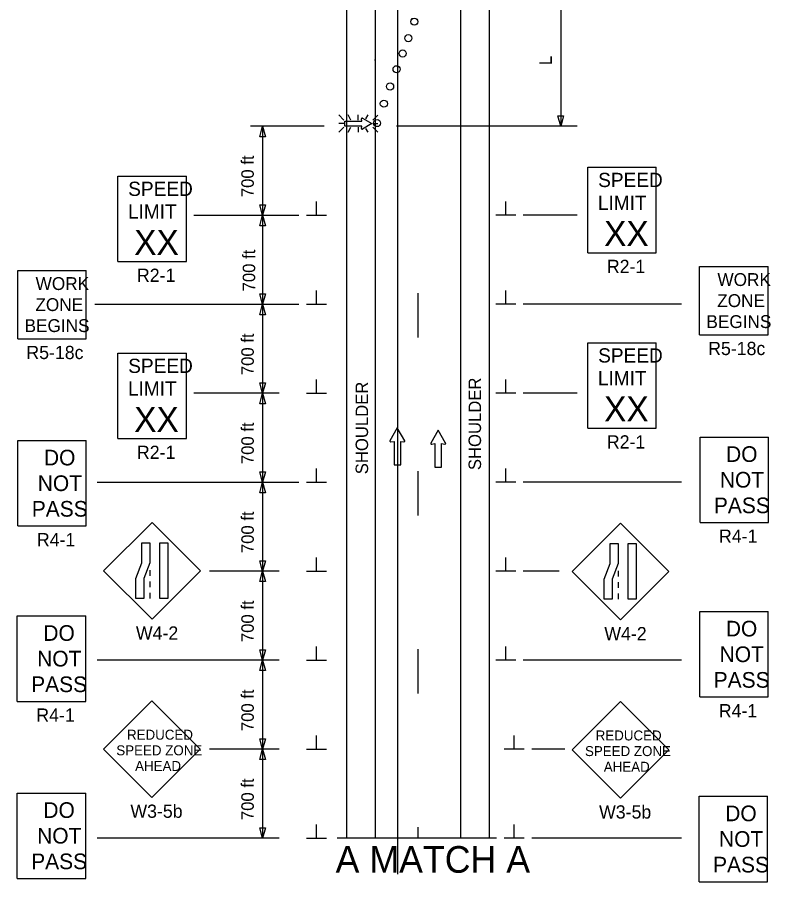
# Model space of a CAD drawing. Extents: x 15262 to 18126, y 1908 to 6555.
# Drawn here: x 15368.1 to 15791.2, y 2404.3 to 2890 of the extents above; entities that cross this region are included whole.
import ezdxf

# ---------------------------------------------------------------- set-up
doc = ezdxf.new("R2010")
doc.units = 0
for name, color, linetype in [('ALI_LEGAL_EX', 7, 'Continuous'), ('MT_SCRATCH_LEVEL_E', 7, 'Continuous'), ('PAVT_EDGE_EX', 7, 'Continuous'), ('TRAFFIC_SIGNS_PR', 7, 'Continuous'), ('TYPICAL_TEXT_DIMEN_PR', 7, 'Continuous')]:
    doc.layers.add(name, color=color, linetype=linetype)

msp = doc.modelspace()

# ---------------------------------------------------------------- linework, layer by layer
at = {"layer": 'ALI_LEGAL_EX'}
msp.add_line((15581.68, 3237.79), (15581.68, 2408.6), dxfattribs=at)
for points in [[(15593, 2735), (15593, 2710)], [(15593, 2635), (15593, 2610)], [(15593, 2535), (15593, 2510)], [(15593, 2435), (15593, 2428.74)]]:
    msp.add_lwpolyline(points, dxfattribs=at)
at = {"layer": 'MT_SCRATCH_LEVEL_E'}
for p, q in [((15581.51, 2659.29), (15577.39, 2652.05)), ((15585.65, 2652.05), (15581.51, 2659.29)), ((15604.48, 2658.02), (15600.37, 2650.78)), ((15608.63, 2650.78), (15604.48, 2658.02)), ((15577.88, 2651.37), (15579.65, 2651.68)), ((15579.65, 2651.68), (15579.65, 2638.43)), ((15583.4, 2638.43), (15583.4, 2651.68)), ((15583.4, 2651.68), (15585.17, 2651.37)), ((15600.85, 2650.1), (15602.63, 2650.41)), ((15602.63, 2650.41), (15602.63, 2637.16)), ((15606.37, 2637.16), (15606.37, 2650.41)), ((15606.37, 2650.41), (15608.15, 2650.1)), ((15579.65, 2638.43), (15583.4, 2638.43)), ((15602.63, 2637.16), (15606.37, 2637.16))]:
    msp.add_line(p, q, dxfattribs=at)
for centre, start, end in [((15577.8, 2651.83), 150.4248, 279.9638), ((15585.24, 2651.83), 260.0362, 29.7731), ((15600.78, 2650.56), 150.4248, 279.9638), ((15608.22, 2650.56), 260.0362, 29.7731)]:
    msp.add_arc(centre, 0.463, start, end, dxfattribs=at)
at = {"layer": 'PAVT_EDGE_EX'}
for p, q in [((15553, 3162.29), (15553, 2428.74)), ((15569, 3162.29), (15569, 2428.74)), ((15617, 3162.29), (15617, 2428.74)), ((15633, 3163.21), (15633, 2428.74)), ((15589.94, 2889.37), (15589.89, 2889.49)), ((15568.93, 2865.92), (15568.88, 2866.04))]:
    msp.add_line(p, q, dxfattribs=at)
at = {"layer": 'TRAFFIC_SIGNS_PR'}
for p, q in [((15551.53, 2832.24), (15548.71, 2835.07)), ((15555.48, 2832.24), (15553.85, 2835.07)), ((15559.62, 2832.24), (15559.62, 2835.07)), ((15563.8, 2832.88), (15565.06, 2835.07)), ((15570.52, 2835.06), (15567.7, 2832.24)), ((15551.53, 2830.21), (15548.71, 2830.21)), ((15551.53, 2828.18), (15548.71, 2825.36)), ((15553.83, 2825.36), (15555.46, 2828.18)), ((15559.62, 2828.18), (15559.62, 2825.36)), ((15565.09, 2825.36), (15563.88, 2827.45)), ((15567.7, 2830.21), (15570.52, 2830.21)), ((15570.52, 2825.36), (15567.7, 2828.18)), ((15688.51, 2805.71), (15726.91, 2805.71)), ((15688.51, 2757.71), (15688.51, 2805.71)), ((15726.91, 2757.71), (15726.91, 2805.71)), ((15424.65, 2800.74), (15463.05, 2800.74)), ((15424.65, 2752.74), (15424.65, 2800.74)), ((15463.05, 2752.74), (15463.05, 2800.74)), ((15688.51, 2757.71), (15726.91, 2757.71)), ((15424.65, 2752.74), (15463.05, 2752.74)), ((15751.25, 2711.62), (15751.25, 2750.02)), ((15751.25, 2750.02), (15789.65, 2750.02)), ((15789.65, 2711.62), (15789.65, 2750.02)), ((15368.42, 2709.37), (15368.42, 2747.77)), ((15368.42, 2747.77), (15406.82, 2747.77)), ((15406.82, 2709.37), (15406.82, 2747.77)), ((15751.25, 2711.62), (15789.65, 2711.62)), ((15368.42, 2709.37), (15406.82, 2709.37)), ((15688.51, 2707.12), (15726.91, 2707.12)), ((15688.51, 2659.12), (15688.51, 2707.12)), ((15726.91, 2659.12), (15726.91, 2707.12)), ((15424.65, 2701.27), (15463.05, 2701.27)), ((15424.65, 2653.27), (15424.65, 2701.27)), ((15463.05, 2653.27), (15463.05, 2701.27)), ((15688.51, 2659.12), (15726.91, 2659.12)), ((15368.48, 2604.2), (15368.48, 2652.2)), ((15368.48, 2652.2), (15406.88, 2652.2)), ((15406.88, 2604.2), (15406.88, 2652.2)), ((15424.65, 2653.27), (15463.05, 2653.27)), ((15751.47, 2606.14), (15751.47, 2654.14)), ((15751.47, 2654.14), (15789.87, 2654.14)), ((15789.87, 2606.14), (15789.87, 2654.14)), ((15368.48, 2604.2), (15406.88, 2604.2)), ((15443.79, 2606.06), (15416.63, 2578.91)), ((15470.94, 2578.91), (15443.79, 2606.06)), ((15706.79, 2605.7), (15679.64, 2578.54)), ((15733.95, 2578.54), (15706.79, 2605.7)), ((15751.47, 2606.14), (15789.87, 2606.14)), ((15416.63, 2578.91), (15443.79, 2551.75)), ((15442.54, 2579.4), (15442.54, 2576.2)), ((15443.79, 2551.75), (15470.94, 2578.91)), ((15705.55, 2579.03), (15705.55, 2575.83)), ((15679.64, 2578.54), (15706.79, 2551.39)), ((15706.79, 2551.39), (15733.95, 2578.54)), ((15442.54, 2573), (15442.54, 2569.8)), ((15705.55, 2572.63), (15705.55, 2569.43)), ((15442.54, 2566.6), (15442.54, 2563.4)), ((15705.55, 2566.23), (15705.55, 2563.03)), ((15751.34, 2508.09), (15751.34, 2556.09)), ((15751.34, 2556.09), (15789.74, 2556.09)), ((15789.74, 2508.09), (15789.74, 2556.09)), ((15368.14, 2505.63), (15368.14, 2553.63)), ((15368.14, 2553.63), (15406.54, 2553.63)), ((15406.54, 2505.63), (15406.54, 2553.63)), ((15751.34, 2508.09), (15789.74, 2508.09)), ((15368.14, 2505.63), (15406.54, 2505.63)), ((15443.68, 2505.95), (15416.53, 2478.8)), ((15470.84, 2478.8), (15443.68, 2505.95)), ((15706.83, 2505.53), (15679.68, 2478.37)), ((15733.99, 2478.37), (15706.83, 2505.53)), ((15416.53, 2478.8), (15443.68, 2451.64)), ((15443.68, 2451.64), (15470.84, 2478.8)), ((15679.68, 2478.37), (15706.83, 2451.22)), ((15706.83, 2451.22), (15733.99, 2478.37)), ((15368.14, 2406.14), (15368.14, 2454.14)), ((15368.14, 2454.14), (15406.54, 2454.14)), ((15406.54, 2406.14), (15406.54, 2454.14)), ((15751, 2404.3), (15751, 2452.3)), ((15751, 2452.3), (15789.4, 2452.3)), ((15789.4, 2404.3), (15789.4, 2452.3)), ((15368.14, 2406.14), (15406.54, 2406.14)), ((15751, 2404.3), (15789.4, 2404.3))]:
    msp.add_line(p, q, dxfattribs=at)
for points in [[(15561.44, 2827.53), (15561.67, 2828.83), (15551.95, 2828.83), (15551.95, 2831.57), (15561.67, 2831.57), (15561.44, 2832.87)], [(15561.94, 2833.23), (15567.25, 2830.21), (15561.94, 2827.17)]]:
    msp.add_lwpolyline(points, dxfattribs=at)
for points in [[(15442.54, 2594.64), (15442.54, 2583.46), (15439.2, 2574.58), (15439.2, 2563.4), (15434.7, 2563.4), (15434.7, 2574.58), (15438.05, 2583.46), (15438.05, 2594.64)], [(15452.68, 2594.64), (15452.68, 2563.4), (15448.18, 2563.4), (15448.18, 2594.64)], [(15705.55, 2594.28), (15705.55, 2583.1), (15702.2, 2574.22), (15702.2, 2563.03), (15697.71, 2563.03), (15697.71, 2574.22), (15701.05, 2583.1), (15701.05, 2594.28)], [(15715.68, 2594.28), (15715.68, 2563.03), (15711.19, 2563.03), (15711.19, 2594.28)]]:
    msp.add_lwpolyline(points, close=True, dxfattribs=at)
for centre in [(15591.08, 2887.5), (15587.71, 2878.22), (15584.49, 2869.63), (15581.11, 2860.76), (15577.45, 2851.08), (15573.97, 2841.41), (15570.12, 2830.52)]:
    msp.add_circle(centre, 2, dxfattribs=at)
for centre, start, end in [((15561.78, 2832.93), 61.1084, 189.2692), ((15561.78, 2827.47), 170.0407, 298.5167)]:
    msp.add_arc(centre, 0.341, start, end, dxfattribs=at)
at = {"layer": 'TYPICAL_TEXT_DIMEN_PR'}
for p, q in [((15673.27, 2897.71), (15673.27, 2828.75)), ((15673.25, 2828.74), (15671.68, 2834.61)), ((15671.68, 2834.61), (15673.25, 2834.61)), ((15673.25, 2834.61), (15674.82, 2834.61)), ((15674.82, 2834.61), (15673.25, 2828.74)), ((15540.45, 2828.74), (15499.13, 2828.74)), ((15504.31, 2822.88), (15505.88, 2828.74)), ((15505.88, 2828.74), (15505.88, 2778.74)), ((15505.88, 2828.74), (15507.45, 2822.88)), ((15682.48, 2828.74), (15581.07, 2828.74)), ((15505.88, 2822.88), (15504.31, 2822.88)), ((15507.45, 2822.88), (15505.88, 2822.88)), ((15505.88, 2778.74), (15504.31, 2784.61)), ((15504.31, 2784.61), (15505.88, 2784.61)), ((15505.88, 2784.61), (15507.45, 2784.61)), ((15507.45, 2784.61), (15505.88, 2778.74)), ((15536.12, 2778.74), (15536.12, 2786.53)), ((15642.37, 2778.74), (15642.37, 2786.53)), ((15467.25, 2778.74), (15526.25, 2778.74)), ((15504.31, 2772.88), (15505.88, 2778.74)), ((15504.31, 2772.88), (15505.88, 2778.74)), ((15505.88, 2778.74), (15505.88, 2728.74)), ((15505.88, 2778.74), (15507.45, 2772.88)), ((15505.88, 2778.74), (15507.45, 2772.88)), ((15530.5, 2778.74), (15541.75, 2778.74)), ((15648, 2778.74), (15636.75, 2778.74)), ((15682.48, 2778.74), (15652.25, 2778.74)), ((15505.88, 2772.88), (15504.31, 2772.88)), ((15505.88, 2772.88), (15504.31, 2772.88)), ((15507.45, 2772.88), (15505.88, 2772.88)), ((15507.45, 2772.88), (15505.88, 2772.88)), ((15505.88, 2728.74), (15504.31, 2734.61)), ((15504.31, 2734.61), (15505.88, 2734.61)), ((15505.88, 2728.74), (15504.31, 2734.61)), ((15504.31, 2734.61), (15505.88, 2734.61)), ((15505.88, 2734.61), (15507.45, 2734.61)), ((15507.45, 2734.61), (15505.88, 2728.74)), ((15505.88, 2734.61), (15507.45, 2734.61)), ((15507.45, 2734.61), (15505.88, 2728.74)), ((15536.12, 2728.74), (15536.12, 2736.53)), ((15642.37, 2728.74), (15642.37, 2736.53)), ((15411.63, 2728.74), (15526.25, 2728.74)), ((15504.31, 2722.88), (15505.88, 2728.74)), ((15505.88, 2728.74), (15505.88, 2678.74)), ((15505.88, 2728.74), (15507.45, 2722.88)), ((15530.5, 2728.74), (15541.75, 2728.74)), ((15648, 2728.74), (15636.75, 2728.74)), ((15741.04, 2728.74), (15652.25, 2728.74)), ((15505.88, 2722.88), (15504.31, 2722.88)), ((15507.45, 2722.88), (15505.88, 2722.88)), ((15536.12, 2678.74), (15536.12, 2686.53)), ((15642.37, 2678.74), (15642.37, 2686.53)), ((15505.88, 2678.74), (15504.31, 2684.61)), ((15504.31, 2684.61), (15505.88, 2684.61)), ((15505.88, 2684.61), (15507.45, 2684.61)), ((15507.45, 2684.61), (15505.88, 2678.74)), ((15515.11, 2678.74), (15467.25, 2678.74)), ((15504.31, 2672.88), (15505.88, 2678.74)), ((15505.88, 2678.74), (15505.88, 2628.74)), ((15505.88, 2678.74), (15507.45, 2672.88)), ((15530.5, 2678.74), (15541.75, 2678.74)), ((15648, 2678.74), (15636.75, 2678.74)), ((15682.48, 2678.74), (15652.25, 2678.74)), ((15505.88, 2672.88), (15504.31, 2672.88)), ((15507.45, 2672.88), (15505.88, 2672.88)), ((15505.88, 2628.74), (15504.31, 2634.61)), ((15504.31, 2634.61), (15505.88, 2634.61)), ((15505.88, 2628.74), (15504.31, 2634.61)), ((15504.31, 2634.61), (15505.88, 2634.61)), ((15505.88, 2634.61), (15507.45, 2634.61)), ((15507.45, 2634.61), (15505.88, 2628.74)), ((15505.88, 2634.61), (15507.45, 2634.61)), ((15507.45, 2634.61), (15505.88, 2628.74)), ((15536.12, 2628.74), (15536.12, 2636.53)), ((15642.37, 2628.74), (15642.37, 2636.53)), ((15412.92, 2628.74), (15526.25, 2628.74)), ((15504.31, 2622.88), (15505.88, 2628.74)), ((15505.88, 2628.74), (15505.88, 2578.74)), ((15505.88, 2628.74), (15507.45, 2622.88)), ((15530.5, 2628.74), (15541.75, 2628.74)), ((15648, 2628.74), (15636.75, 2628.74)), ((15741.04, 2628.74), (15652.25, 2628.74)), ((15505.88, 2622.88), (15504.31, 2622.88)), ((15507.45, 2622.88), (15505.88, 2622.88)), ((15505.88, 2578.74), (15504.31, 2584.61)), ((15504.31, 2584.61), (15505.88, 2584.61)), ((15505.88, 2584.61), (15507.45, 2584.61)), ((15507.45, 2584.61), (15505.88, 2578.74)), ((15536.12, 2578.74), (15536.12, 2586.53)), ((15642.37, 2578.74), (15642.37, 2586.53)), ((15515.11, 2578.74), (15476.05, 2578.74)), ((15504.31, 2572.88), (15505.88, 2578.74)), ((15505.88, 2578.74), (15507.45, 2572.88)), ((15505.88, 2578.74), (15505.88, 2528.74)), ((15530.5, 2578.74), (15541.75, 2578.74)), ((15648, 2578.74), (15636.75, 2578.74)), ((15672.46, 2578.74), (15652.25, 2578.74)), ((15505.88, 2572.88), (15504.31, 2572.88)), ((15507.45, 2572.88), (15505.88, 2572.88)), ((15536.12, 2528.74), (15536.12, 2536.53)), ((15642.37, 2528.74), (15642.37, 2536.53)), ((15505.88, 2528.74), (15504.31, 2534.61)), ((15504.31, 2534.61), (15505.88, 2534.61)), ((15505.88, 2534.61), (15507.45, 2534.61)), ((15507.45, 2534.61), (15505.88, 2528.74)), ((15515.11, 2528.74), (15412.92, 2528.74)), ((15504.31, 2522.88), (15505.88, 2528.74)), ((15505.88, 2528.74), (15507.45, 2522.88)), ((15505.88, 2528.74), (15505.88, 2478.74)), ((15530.5, 2528.74), (15541.75, 2528.74)), ((15648, 2528.74), (15636.75, 2528.74)), ((15741.04, 2528.74), (15652.25, 2528.74)), ((15505.88, 2522.88), (15504.31, 2522.88)), ((15507.45, 2522.88), (15505.88, 2522.88)), ((15505.88, 2478.74), (15504.31, 2484.61)), ((15504.31, 2484.61), (15505.88, 2484.61)), ((15505.88, 2484.61), (15507.45, 2484.61)), ((15507.45, 2484.61), (15505.88, 2478.74)), ((15536.12, 2478.74), (15536.12, 2486.53)), ((15647.13, 2478.74), (15647.13, 2486.53)), ((15515.11, 2478.74), (15476.05, 2478.74)), ((15504.31, 2472.88), (15505.88, 2478.74)), ((15505.88, 2478.74), (15507.45, 2472.88)), ((15505.88, 2478.74), (15505.88, 2428.74)), ((15530.5, 2478.74), (15541.75, 2478.74)), ((15652.75, 2478.74), (15641.5, 2478.74)), ((15675.59, 2478.74), (15657.07, 2478.74)), ((15505.88, 2472.88), (15504.31, 2472.88)), ((15507.45, 2472.88), (15505.88, 2472.88)), ((15505.88, 2428.74), (15504.31, 2434.61)), ((15504.31, 2434.61), (15505.88, 2434.61)), ((15505.88, 2434.61), (15507.45, 2434.61)), ((15507.45, 2434.61), (15505.88, 2428.74)), ((15536.12, 2428.74), (15536.12, 2436.53)), ((15647.13, 2428.74), (15647.13, 2436.53)), ((15515.11, 2428.74), (15412.92, 2428.74)), ((15530.5, 2428.74), (15541.75, 2428.74)), ((15637.19, 2428.74), (15547.76, 2428.74)), ((15652.75, 2428.74), (15641.5, 2428.74)), ((15741.04, 2428.74), (15657.07, 2428.74))]:
    msp.add_line(p, q, dxfattribs=at)

# ---------------------------------------------------------------- texts
at = {"layer": 'TRAFFIC_SIGNS_PR'}
for s, height, p in [('SPEED', 8, (15694.28, 2794.58)), ('SPEED', 8, (15430.42, 2789.6)), ('LIMIT', 8, (15694.12, 2781.78)), ('LIMIT', 8, (15430.26, 2776.8)), ('XX', 14.031, (15697.62, 2761.47)), ('XX', 14.031, (15433.77, 2756.5)), ('R2-1', 7.44, (15699.19, 2746.27)), ('WORK', 7.217, (15378.42, 2736.74)), ('R2-1', 7.44, (15435.33, 2741.3)), ('WORK', 7.217, (15761.25, 2738.99)), ('ZONE', 7.217, (15761.13, 2727.17)), ('ZONE', 7.217, (15378.3, 2724.93)), ('BEGINS', 7.217, (15372.23, 2713.12)), ('BEGINS', 7.217, (15755.06, 2715.37)), ('R5-18c', 7.44, (15373.23, 2697.93)), ('R5-18c', 7.44, (15756.06, 2700.18)), ('SPEED', 8, (15694.28, 2695.99)), ('SPEED', 8, (15430.42, 2690.14)), ('LIMIT', 8, (15694.12, 2683.19)), ('LIMIT', 8, (15430.26, 2677.34)), ('XX', 14.031, (15697.62, 2662.88)), ('XX', 14.031, (15433.77, 2657.03)), ('R2-1', 7.44, (15699.19, 2647.68)), ('DO', 8.8, (15383.11, 2638.2)), ('R2-1', 7.44, (15435.33, 2641.83)), ('DO', 8.8, (15766.1, 2640.15)), ('NOT', 8.8, (15379.62, 2623.8)), ('NOT', 8.8, (15762.61, 2625.75)), ('PASS', 8.8, (15376.27, 2609.4)), ('PASS', 8.8, (15759.26, 2611.35)), ('R4-1', 7.44, (15379.15, 2592.76)), ('R4-1', 7.44, (15762.15, 2594.71)), ('DO', 8.8, (15765.97, 2542.09)), ('DO', 8.8, (15382.77, 2539.63)), ('W4-2', 7.44, (15434.74, 2540.32)), ('W4-2', 7.44, (15697.75, 2539.95)), ('NOT', 8.8, (15762.49, 2527.69)), ('NOT', 8.8, (15379.28, 2525.23)), ('PASS', 8.8, (15759.14, 2513.29)), ('PASS', 8.8, (15375.93, 2510.83)), ('R4-1', 7.44, (15378.82, 2494.19)), ('R4-1', 7.44, (15762.02, 2496.65)), ('REDUCED', 5.6, (15429.74, 2484.11)), ('REDUCED', 5.6, (15692.89, 2483.68)), ('SPEED ZONE', 5.6, (15423.73, 2475.31)), ('SPEED ZONE', 5.6, (15686.88, 2474.88)), ('AHEAD', 5.6, (15434.29, 2466.51)), ('AHEAD', 5.6, (15697.44, 2466.08)), ('DO', 8.8, (15382.77, 2440.14)), ('W3-5b', 7.44, (15431.64, 2440.2)), ('W3-5b', 7.44, (15694.79, 2439.78)), ('DO', 8.8, (15765.63, 2438.3)), ('NOT', 8.8, (15379.28, 2425.74)), ('NOT', 8.8, (15762.14, 2423.9)), ('PASS', 8.8, (15375.93, 2411.34)), ('PASS', 8.8, (15758.79, 2409.5))]:
    msp.add_text(s, height=height, dxfattribs=at).set_placement(p)
at = {"layer": 'TYPICAL_TEXT_DIMEN_PR'}
for s, p in [('L', (15668.29, 2863.1)), ('700 ft', (15500.92, 2788.91)), ('700 ft', (15501.7, 2735.97)), ('700 ft', (15500.92, 2688.91)), ('SHOULDER', (15628.53, 2635.54)), ('SHOULDER', (15565.1, 2633.23)), ('700 ft', (15500.92, 2638.91)), ('700 ft', (15500.92, 2588.91)), ('700 ft', (15500.92, 2538.91)), ('700 ft', (15500.92, 2488.91)), ('700 ft', (15500.92, 2438.91))]:
    msp.add_text(s, height=7, rotation=90, dxfattribs=at).set_placement(p)
msp.add_text('A MATCH A', height=15, dxfattribs=at).set_placement((15546.86, 2409.33))

doc.saveas('drawing.dxf')
